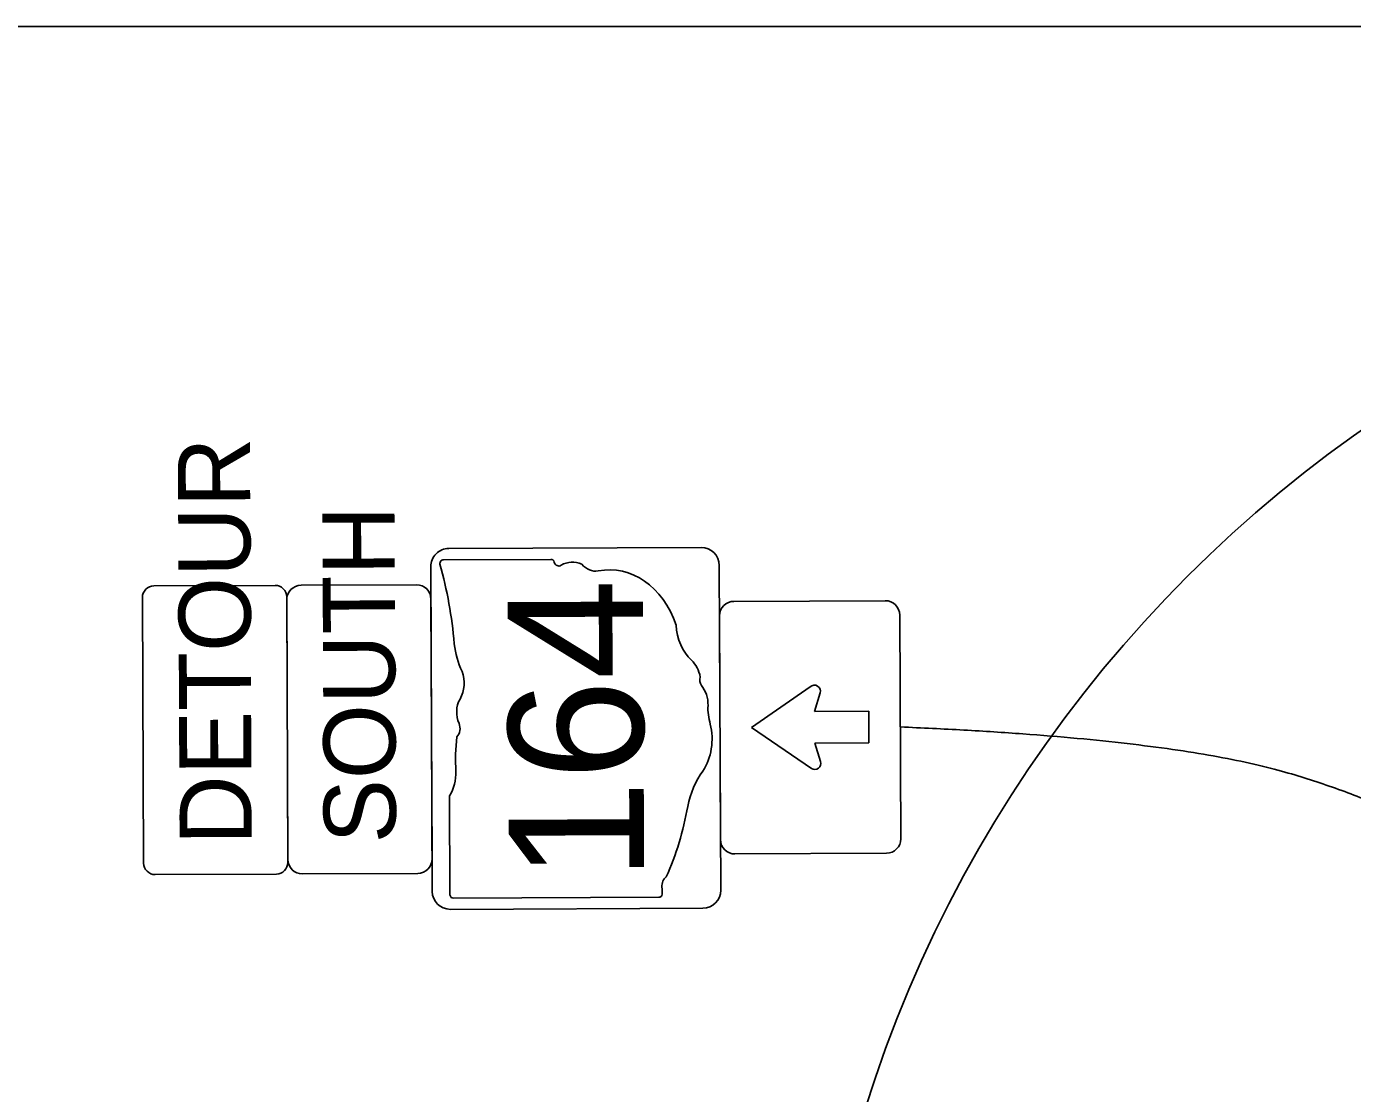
# Model space of a CAD drawing. Extents: x -740 to 1519, y 0 to 440.
# Drawn here: x 350.9 to 442.8, y 146.1 to 220 of the extents above; entities that cross this region are included whole.
import ezdxf

# ---------------------------------------------------------------- set-up
doc = ezdxf.new("R2010")
doc.units = 0
for name, color, linetype in [('GM_X_Minor_River', 7, 'Continuous'), ('GM_X_Section', 7, 'Continuous'), ('SH_Data', 7, 'Continuous')]:
    doc.layers.add(name, color=color, linetype=linetype)

msp = doc.modelspace()

# ---------------------------------------------------------------- linework, layer by layer
at = {"layer": 'GM_X_Minor_River'}
for p, q in [((387.245, 183.083), (379.8, 183.05)), ((387.243, 183.081), (387.245, 183.083)), ((369.934, 181.288), (377.934, 181.324)), ((369.018, 162.284), (368.938, 180.284)), ((378.938, 180.329), (379.018, 162.329)), ((399.939, 180.172), (410.439, 180.219)), ((399.013, 163.668), (398.944, 179.168)), ((411.443, 179.223), (411.512, 163.723)), ((401.166, 171.427), (405.234, 174.241)), ((405.929, 173.825), (405.536, 172.54)), ((405.536, 172.54), (409.286, 172.557)), ((409.286, 172.557), (409.296, 170.369)), ((405.317, 168.603), (401.166, 171.427)), ((409.296, 170.369), (405.546, 170.352)), ((405.546, 170.352), (405.95, 169.072)), ((380.226, 166.709), (380.256, 159.846)), ((410.517, 162.719), (400.017, 162.672)), ((378.023, 161.324), (370.023, 161.289)), ((380.502, 159.616), (394.733, 159.679))]:
    msp.add_line(p, q, dxfattribs=at)
for points in [[(380.173, 183.834), (397.672, 183.912)], [(379.028, 160.079), (378.928, 182.579)], [(398.928, 182.668), (399.028, 160.168)], [(368.134, 181.28), (359.734, 181.243)], [(358.937, 180.439), (359.019, 162.04)], [(369.019, 162.084), (368.937, 180.484)], [(359.823, 161.243), (368.223, 161.281)], [(397.784, 158.912), (380.284, 158.834)]]:
    msp.add_lwpolyline(points, dxfattribs=at)
for centre, radius, start, end in [((397.678, 182.662), 1.25, 0.25509, 90.25509), ((380.178, 182.584), 1.25, 90.25509, 180.25509), ((359.737, 180.443), 0.8, 90.25509, 180.25509), ((368.137, 180.48), 0.8, 0.25509, 90.25509), ((369.939, 180.288), 1, 90.25509, 180.25509), ((377.939, 180.324), 1, 0.25509, 90.25509), ((410.443, 179.219), 1, 0.25509, 90.25509), ((399.943, 179.172), 1, 90.25509, 180.25509), ((405.53, 173.947), 0.417, 343.05049, 135.26465), ((405.552, 168.947), 0.417, 235.66631, 17.4597), ((400.012, 163.672), 1, 180.25509, 270.25509), ((410.512, 163.719), 1, 270.25509, 0.25509), ((359.819, 162.043), 0.8, 180.25509, 270.25509), ((368.219, 162.081), 0.8, 270.25509, 0.25509), ((370.019, 162.288), 1, 180.25509, 270.25509), ((378.019, 162.324), 1, 270.25509, 0.25509), ((380.278, 160.084), 1.25, 180.25509, 270.25509), ((397.778, 160.162), 1.25, 270.25509, 0.25509)]:
    msp.add_arc(centre, radius, start, end, dxfattribs=at)
for centre, major_axis, start_param, end_param in [((379.771, 182.79), (-0.001, 0.261), 6.141152, 7.989035), ((387.275, 182.805), (-0.001, 0.279), 5.05454, 6.418171), ((388.744, 180.461), (-0.011, 2.424), 5.934695, 6.695948), ((360.789, 174.617), (-0.111, 24.854), 4.814394, 5.042369), ((387.791, 183.025), (-0.002, 0.404), 1.883978, 3.671073), ((390.356, 184.032), (-0.008, 1.764), 2.387724, 3.262537), ((391.338, 176.145), (-0.028, 6.217), 5.101752, 6.440018), ((398.643, 178.799), (-0.015, 3.405), 1.647645, 2.488434), ((384.523, 177.893), (-0.022, 5), 1.699011, 2.107814), ((396.046, 174.473), (-0.009, 2.008), 4.937069, 5.64225), ((379.721, 174.515), (-0.008, 1.9), 4.081561, 5.145723), ((398.001, 174.71), (-0.002, 0.535), 1.147584, 2.315152), ((396.631, 172.986), (-0.008, 1.899), 4.691044, 5.507374), ((381.986, 172.487), (-0.007, 1.58), 0.950623, 2.079405), ((400.486, 172.743), (-0.013, 2.928), 1.495662, 1.94098), ((380.346, 171.364), (-0.003, 0.76), 3.836095, 5.185415), ((395.576, 170.662), (-0.016, 3.563), 4.026481, 4.996735), ((388.204, 169.252), (-0.042, 9.454), 1.404758, 1.657858), ((378.566, 168.336), (-0.012, 2.634), 4.042523, 4.731795), ((401.104, 164.613), (-0.025, 5.616), 0.823519, 1.323587), ((382.723, 169.883), (-0.08, 17.948), 4.195997, 4.488961), ((395.551, 160.423), (-0.003, 0.754), 0.519207, 1.627899), ((393.307, 159.985), (-0.009, 2.09), 4.665946, 4.897461), ((380.471, 159.884), (-0.001, 0.272), 1.712693, 3.28349), ((394.763, 159.95), (-0.001, 0.274), 3.00124, 4.508301)]:
    msp.add_ellipse(centre, major_axis=major_axis, ratio=0.8, start_param=start_param, end_param=end_param, dxfattribs=at)
at = {"layer": 'GM_X_Section'}
msp.add_line((30, 220), (640, 220), dxfattribs=at)
at = {"layer": 'SH_Data'}
msp.add_circle((495, 118.25), 90, dxfattribs=at)
msp.add_open_spline([(411.478, 171.473), (430.143, 170.678), (446.411, 165.935), (458.908, 157.743), (473.991, 149.227), (486.596, 132.734), (491.889, 128.222)], degree=2, dxfattribs=at)

# ---------------------------------------------------------------- texts
at = {"layer": 'GM_X_Minor_River'}
for s, height, p in [('DETOUR', 5, (366.514, 163.305)), ('SOUTH', 5, (376.513, 163.404)), ('164', 9.375, (393.724, 160.822))]:
    msp.add_text(s, height=height, rotation=90.25509, dxfattribs=at).set_placement(p)

doc.saveas('drawing.dxf')
